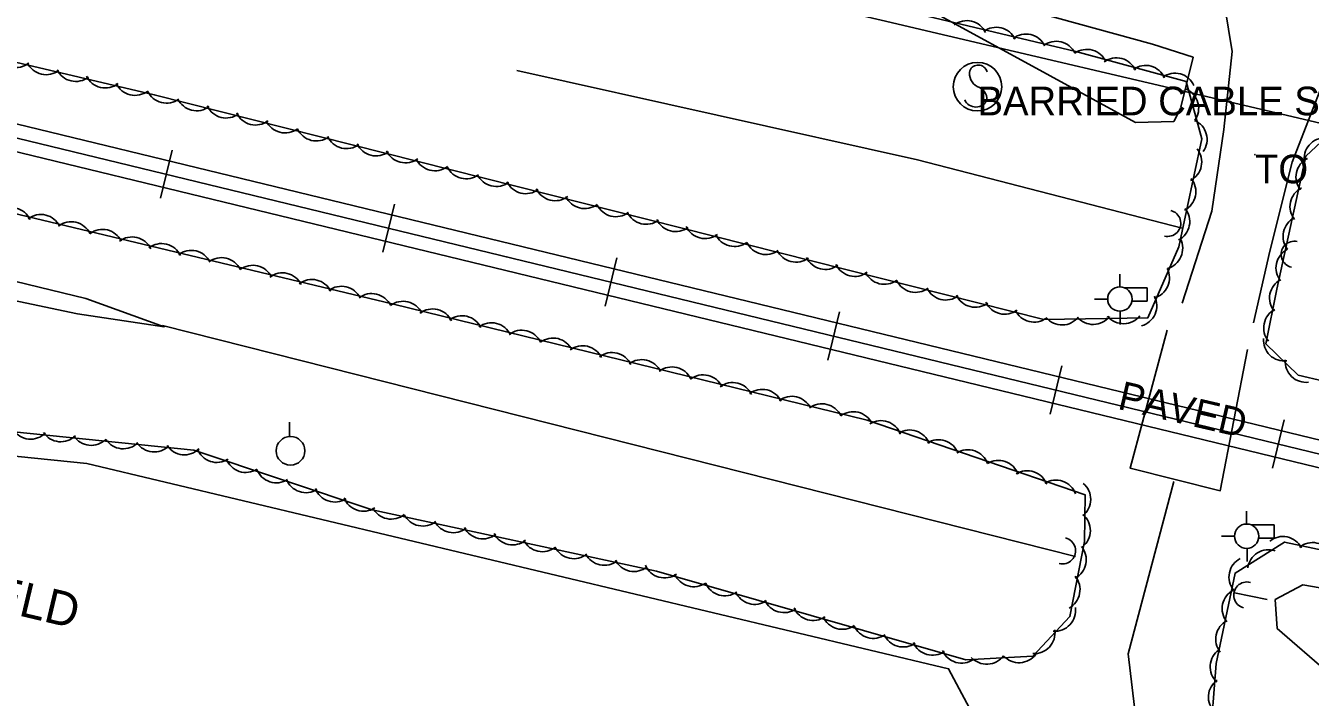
# Model space of a CAD drawing. Extents: x 1441650 to 1491889, y 345904 to 358319.
# Drawn here: x 1454014.1 to 1454238.7, y 352365.8 to 352483.1 of the extents above; entities that cross this region are included whole.
import ezdxf

# ---------------------------------------------------------------- set-up
doc = ezdxf.new("R2010")
doc.units = 0
for name, color, linetype in [('S_CROSS_DRAIN', 7, 'Continuous'), ('S_DITCHLINE', 7, 'Continuous'), ('S_GRAVEL_ROAD', 7, 'Continuous'), ('S_MISC_BOUNDARY', 7, 'Continuous'), ('S_MISC_BOUNDARY_ANNOT', 7, 'Continuous'), ('S_MSC_PT_SYM', 7, 'Continuous'), ('S_PARKING', 7, 'Continuous'), ('S_PARKING_ANNOT', 7, 'Continuous'), ('S_RAILROAD', 7, 'Continuous'), ('S_SIGN', 7, 'Continuous'), ('S_SIGN_ANNOT', 7, 'Continuous'), ('S_STREAM', 7, 'Continuous'), ('S_SURVEY_TEXT_ANNOT', 7, 'Continuous'), ('S_TRAILS', 7, 'Continuous'), ('S_TREE', 7, 'Continuous'), ('S_UTILITY_POLE', 7, 'Continuous')]:
    doc.layers.add(name, color=color, linetype=linetype)

msp = doc.modelspace()

# ---------------------------------------------------------------- linework, layer by layer
at = {"layer": 'S_CROSS_DRAIN'}
for centre, start, end in [((1454213.72, 352448.62), 255.9465, 76.2757), ((1454235.87, 352443.19), 77.6757, 258.0049), ((1454195.33, 352391.41), 256.306, 76.6352), ((1454227.58, 352383.66), 74.8593, 255.1885)]:
    msp.add_arc(centre, 2.3, start, end, dxfattribs=at)
at = {"layer": 'S_DITCHLINE'}
for points in [[(1454009.41, 352529.25), (1454021.93, 352526.19), (1454034.45, 352523.13), (1454046.97, 352520.07), (1454059.49, 352517.01), (1454072.01, 352513.95), (1454084.46, 352511.05), (1454096.91, 352508.15), (1454109.36, 352505.25), (1454121.81, 352502.35), (1454134.26, 352499.45), (1454146.71, 352496.55), (1454159.16, 352493.64), (1454171.6, 352490.74), (1454191.33, 352485.34), (1454211.05, 352479.93), (1454218.16, 352477.61), (1454216.01, 352468.91)], [(1454007.94, 352525.44), (1454020.6, 352522.38), (1454033.27, 352519.33), (1454045.93, 352516.28), (1454058.6, 352513.22), (1454071.26, 352510.17), (1454083.7, 352507.22), (1454096.14, 352504.28), (1454108.58, 352501.33), (1454121.02, 352498.39), (1454133.46, 352495.45), (1454145.9, 352492.5), (1454158.34, 352489.56), (1454170.78, 352486.61), (1454189.44, 352476.43), (1454208.09, 352466.25), (1454214.79, 352466.42), (1454216.02, 352468.81)]]:
    msp.add_lwpolyline(points, dxfattribs=at)
at = {"layer": 'S_GRAVEL_ROAD'}
for points in [[(1454217.36, 352502.05), (1454223.03, 352490.72), (1454224.98, 352478.61), (1454223.55, 352464.99), (1454221.42, 352450.76), (1454216.25, 352434.69)], [(1454228.71, 352431.22), (1454231.59, 352443.76), (1454235.46, 352459.28), (1454240.77, 352472.94), (1454247.94, 352481.75), (1454255.77, 352486.24), (1454264.22, 352491.06)]]:
    msp.add_lwpolyline(points, dxfattribs=at)
at = {"layer": 'S_MISC_BOUNDARY'}
msp.add_lwpolyline([(1454686.77, 352224.39), (1454629.36, 352232.66), (1454608.53, 352232.27), (1454586.68, 352227.2), (1454566.38, 352214.24), (1454512.68, 352151.16), (1454476.34, 352101.87), (1454455.06, 352090.76), (1454436.36, 352088.31), (1454415.71, 352093.38), (1454400.49, 352103.06), (1454359.73, 352141.03), (1454293.57, 352211.64), (1454232.27, 352285.07), (1454203.97, 352317.31), (1454175.42, 352370.8), (1454024.8, 352406.68), (1453982.48, 352410.96), (1453913.66, 352425.74), (1453821.25, 352446.56), (1453775.06, 352443.89), (1453762.03, 352438.86)], dxfattribs=at)
at = {"layer": 'S_MSC_PT_SYM'}
msp.add_lwpolyline([(1454228.99, 352460.61), (1454228.99, 352460.66), (1454228.99, 352460.61), (1454228.94, 352460.61), (1454228.99, 352460.61), (1454228.99, 352460.56), (1454228.99, 352460.61), (1454229.04, 352460.61)], dxfattribs=at)
at = {"layer": 'S_PARKING'}
msp.add_lwpolyline([(1454227.7, 352426.54), (1454222.93, 352401.89), (1454207.17, 352405.82), (1454213.61, 352429.97)], dxfattribs=at)
at = {"layer": 'S_RAILROAD'}
for p, q in [((1454039.71, 352461.41), (1454037.67, 352452.98)), ((1454039.25, 352459.5), (1454039.24, 352459.47)), ((1454038.14, 352454.93), (1454038.16, 352455.03)), ((1454078.59, 352451.98), (1454076.54, 352443.56)), ((1454078.13, 352450.08), (1454078.12, 352450.04)), ((1454077.02, 352445.5), (1454077.04, 352445.6)), ((1454117.46, 352442.56), (1454115.42, 352434.13)), ((1454117, 352440.65), (1454116.99, 352440.61)), ((1454205.37, 352437.49), (1454205.37, 352439.74)), ((1454115.89, 352436.07), (1454115.92, 352436.17)), ((1454203.28, 352435.36), (1454200.95, 352435.36)), ((1454210.17, 352437.34), (1454206.3, 352437.34)), ((1454210.17, 352435.01), (1454210.17, 352437.34)), ((1454156.34, 352433.13), (1454154.3, 352424.7)), ((1454205.45, 352430.94), (1454205.45, 352433.27)), ((1454210.17, 352435.01), (1454207.46, 352435.01)), ((1454155.88, 352431.22), (1454155.87, 352431.18)), ((1454154.77, 352426.64), (1454154.79, 352426.74)), ((1454195.22, 352423.7), (1454193.17, 352415.27)), ((1454194.75, 352421.79), (1454194.74, 352421.76)), ((1454193.64, 352417.22), (1454193.67, 352417.32)), ((1454234.09, 352414.27), (1454232.05, 352405.84)), ((1454233.63, 352412.36), (1454233.62, 352412.33)), ((1454232.52, 352407.79), (1454232.54, 352407.89)), ((1454227.53, 352396.06), (1454227.53, 352398.31)), ((1454232.33, 352395.91), (1454228.46, 352395.91)), ((1454232.33, 352393.58), (1454232.33, 352395.91)), ((1454225.44, 352393.93), (1454223.11, 352393.93)), ((1454232.33, 352393.58), (1454229.62, 352393.58)), ((1454227.61, 352389.51), (1454227.61, 352391.84))]:
    msp.add_line(p, q, dxfattribs=at)
for points in [[(1453358.93, 352624.5), (1454392.41, 352373.86)], [(1453358.37, 352622.19), (1454391.85, 352371.55)], [(1453357.82, 352619.92), (1454391.3, 352369.28)], [(1454038.66, 352457.21), (1454038.69, 352457.2)], [(1454077.54, 352447.78), (1454077.57, 352447.77)], [(1454116.41, 352438.35), (1454116.44, 352438.34)], [(1454155.29, 352428.92), (1454155.32, 352428.91)], [(1454194.17, 352419.49), (1454194.19, 352419.49)], [(1454233.04, 352410.07), (1454233.07, 352410.06)]]:
    msp.add_lwpolyline(points, dxfattribs=at)
for centre in [(1454205.37, 352435.38), (1454227.53, 352393.95)]:
    msp.add_circle(centre, 2.13, dxfattribs=at)
at = {"layer": 'S_SIGN'}
msp.add_circle((1454180.49, 352472.48), 4.24, dxfattribs=at)
for centre, radius, start, end in [((1454180.61, 352474.64), 1.62, 16.5258, 156.8957), ((1454181.65, 352474.74), 2.55, 167.1196, 241.9813), ((1454179.78, 352470.2), 2.38, 358.6529, 73.7063), ((1454180.22, 352471.09), 2.17, 204.641, 335.359)]:
    msp.add_arc(centre, radius, start, end, dxfattribs=at)
at = {"layer": 'S_STREAM'}
for points in [[(1453363.01, 352592.55), (1453479.22, 352563.13), (1453550.8, 352550.79), (1453596.82, 352540.94), (1453720.38, 352509.34), (1453785.64, 352491.93), (1453865.72, 352472.98), (1453954.81, 352452.44), (1454024.64, 352435.49), (1454038.35, 352430.55), (1454023.21, 352432.8), (1453961.95, 352445.68), (1453842.37, 352471.78), (1453782.84, 352484.13), (1453730.73, 352495.16), (1453675.19, 352509.46), (1453620.22, 352523.42), (1453558.76, 352539.42), (1453514.08, 352548.87), (1453463.46, 352558.22), (1453415.2, 352569.67), (1453358.6, 352584.91)], [(1454216.26, 352447.75), (1454169.98, 352459.71), (1454099.97, 352475.3)], [(1454038.01, 352430.77), (1454197.64, 352390.4)], [(1454231.13, 352382.87), (1454225.43, 352384.07)], [(1454388.13, 352330.44), (1454301.34, 352351.74), (1454251.8, 352365.75), (1454242.03, 352369.9), (1454232.87, 352377.8), (1454232.52, 352382.87), (1454237.35, 352385.48), (1454257.86, 352381.91), (1454259.92, 352381.42)]]:
    msp.add_lwpolyline(points, dxfattribs=at)
at = {"layer": 'S_TRAILS'}
msp.add_lwpolyline([(1454214.8, 352403.53), (1454206.82, 352373.39), (1454208.65, 352358.18), (1454219.53, 352337.35), (1454259.24, 352301.88), (1454319.02, 352237.9), (1454362.49, 352183.76), (1454390.07, 352144.22), (1454406.89, 352120.14), (1454417.78, 352112.14), (1454435.09, 352106.01), (1454444.99, 352103.91), (1454458.89, 352105.7), (1454468.76, 352112.18), (1454476.58, 352119.44), (1454489.64, 352134.63), (1454511.85, 352168.42), (1454538.41, 352200.75), (1454558.8, 352221.18), (1454581.02, 352236.48), (1454601.95, 352245.1), (1454625.41, 352246.67), (1454663.54, 352240.93), (1454687.4, 352237.14)], dxfattribs=at)
at = {"layer": 'S_TREE'}
for points in [[(1454092.49, 352503.66), (1454197.68, 352478.65), (1454216.97, 352473.38), (1454219.69, 352463.39), (1454215.69, 352444.49), (1454210.26, 352432.12), (1454192.07, 352431.82), (1454036.6, 352471.08), (1453849.04, 352515.24), (1453729.81, 352544.99), (1453559.38, 352584.91), (1453365.35, 352634.52)], [(1453368.83, 352604.5), (1453527.58, 352567.64), (1453619.06, 352545.33), (1453696.34, 352525.35), (1453759.99, 352511.03), (1453842.24, 352490.66), (1453918.96, 352472.74), (1454004.84, 352452.06), (1454078.18, 352434.55), (1454161.22, 352414.2), (1454199.28, 352401.19), (1454199.18, 352393.02), (1454196.64, 352379.91), (1454190.16, 352372.99), (1454178.43, 352372.37), (1454124.39, 352387.86), (1454074.7, 352398.58), (1454043.5, 352408.96), (1453992.52, 352414.17), (1453967.65, 352416.55)], [(1454008.21, 352520.91), (1454020.62, 352517.93), (1454033.03, 352514.95), (1454045.44, 352511.97), (1454057.86, 352508.99), (1454070.27, 352506.01), (1454093.61, 352500.54), (1454116.95, 352495.06), (1454140.3, 352489.58), (1454163.64, 352484.11), (1454186.98, 352478.63), (1454210.33, 352473.15), (1454233.67, 352467.68), (1454257.01, 352462.2)], [(1454008.21, 352520.91), (1454020.62, 352517.93), (1454033.03, 352514.95), (1454045.44, 352511.97), (1454057.86, 352508.99), (1454070.27, 352506.01), (1454093.61, 352500.54), (1454116.95, 352495.06), (1454140.3, 352489.58), (1454163.64, 352484.11), (1454186.98, 352478.63), (1454210.33, 352473.15), (1454233.67, 352467.68), (1454257.01, 352462.2)], [(1454448.79, 352371.34), (1454258.99, 352416.87), (1454236.55, 352422.09), (1454230.87, 352427.54), (1454232.8, 352437.08), (1454237.86, 352460.35), (1454245.03, 352467.03), (1454260.18, 352466.09), (1454313.24, 352456.44), (1454356.46, 352442.02)], [(1454288.48, 352317.63), (1454252.91, 352329.03), (1454235.01, 352340.76), (1454221.11, 352357.5), (1454222.18, 352371.72), (1454225.51, 352387.52), (1454234.15, 352392.92), (1454356.62, 352367.02), (1454510.53, 352327.65), (1454613.3, 352304.23), (1454719.52, 352277.82)]]:
    msp.add_lwpolyline(points, dxfattribs=at)
for centre, start, end in [((1454216.04, 352459.32), 297.2527, 38.8496), ((1454239.79, 352456.71), 116.9239, 218.5208), ((1454215.01, 352454.14), 297.2527, 38.8496), ((1454238.74, 352451.54), 116.9239, 218.5208), ((1454213.95, 352448.94), 297.2527, 38.8496), ((1454237.54, 352446.34), 116.9239, 218.5208), ((1454212.71, 352444.22), 285.4712, 27.0681), ((1454236.3, 352440.83), 116.9239, 218.5208), ((1454210.4, 352439.07), 285.4712, 27.0681), ((1454208.19, 352434.21), 285.4712, 27.0681), ((1454228.08, 352386.82), 117.3066, 218.9035), ((1454226.88, 352381.3), 117.3066, 218.9035), ((1454225.76, 352375.98), 117.3066, 218.9035), ((1454224.8, 352371.12), 124.8998, 226.4967), ((1454224.48, 352365.85), 124.8998, 226.4967)]:
    msp.add_arc(centre, 3.64, start, end, dxfattribs=at)
for centre, major_axis, ratio, start_param, end_param in [((1454178.62, 352480.37), (-3.57, 0.73), 0.999978, 3.793867, 5.567068), ((1454183.78, 352479.22), (-3.57, 0.73), 0.999978, 3.793867, 5.567068), ((1454188.95, 352478.03), (-3.57, 0.73), 0.999978, 3.793867, 5.567068), ((1454194.24, 352476.76), (-3.57, 0.73), 0.999978, 3.793867, 5.567068), ((1454199.62, 352475.36), (-3.51, 0.96), 0.999978, 3.825789, 5.598989), ((1454012.42, 352479.47), (3.55, -0.83), 0.999978, 3.825789, 5.598989), ((1454017.71, 352478.22), (3.55, -0.83), 0.999978, 3.825789, 5.598989), ((1454204.75, 352473.88), (-3.51, 0.96), 0.999978, 3.825789, 5.598989), ((1454209.86, 352472.56), (-3.51, 0.96), 0.999978, 3.825789, 5.598989), ((1454022.88, 352477.04), (3.55, -0.83), 0.999978, 3.825789, 5.598989), ((1454028.04, 352475.9), (3.55, -0.83), 0.999978, 3.825789, 5.598989), ((1454214.99, 352471.2), (-3.51, 0.96), 0.999978, 3.825789, 5.598989), ((1454033.22, 352474.61), (3.55, -0.83), 0.999978, 3.825789, 5.598989), ((1454038.74, 352473.25), (3.29, -1.57), 0.999977, 4.023994, 5.797194), ((1454215.51, 352468.72), (-0.96, 3.51), 0.999994, 3.825789, 5.598989), ((1454044.02, 352471.92), (3.29, -1.57), 0.999977, 4.023994, 5.797194), ((1454049.17, 352470.65), (3.29, -1.57), 0.999977, 4.023994, 5.797194), ((1454054.31, 352469.43), (3.29, -1.57), 0.999977, 4.023994, 5.797194), ((1454059.46, 352468.05), (3.29, -1.57), 0.999977, 4.023994, 5.797194), ((1454064.93, 352466.64), (3.29, -1.57), 0.999977, 4.023994, 5.797194), ((1454216.97, 352463.27), (-0.96, 3.51), 0.999994, 3.825788, 5.598989), ((1454070.2, 352465.3), (3.29, -1.57), 0.999977, 4.023994, 5.797194), ((1454075.35, 352464.04), (3.29, -1.57), 0.999977, 4.023994, 5.797194), ((1454241.23, 352459.9), (-2.67, -2.48), 0.999994, 3.825789, 5.598989), ((1454080.49, 352462.82), (3.29, -1.57), 0.999977, 4.023994, 5.797194), ((1454085.65, 352461.44), (3.29, -1.57), 0.999977, 4.023994, 5.797194), ((1454091.11, 352460.03), (3.29, -1.57), 0.999977, 4.023994, 5.797194), ((1454096.39, 352458.69), (3.29, -1.57), 0.999977, 4.023994, 5.797194), ((1454101.54, 352457.43), (3.29, -1.57), 0.999977, 4.023994, 5.797194), ((1454106.68, 352456.2), (3.29, -1.57), 0.999977, 4.023994, 5.797194), ((1454111.83, 352454.83), (3.29, -1.57), 0.999977, 4.023994, 5.797194), ((1454011.61, 352447.71), (-3.45, 1.18), 0.999612, 3.92082, 5.694021), ((1454117.3, 352453.41), (3.29, -1.57), 0.999977, 4.023994, 5.797194), ((1454016.78, 352446.51), (-3.45, 1.18), 0.999612, 3.92082, 5.694021), ((1454022.07, 352445.24), (-3.45, 1.18), 0.999612, 3.92082, 5.694021), ((1454122.58, 352452.08), (3.29, -1.57), 0.999977, 4.023994, 5.797194), ((1454127.73, 352450.81), (3.29, -1.57), 0.999977, 4.023994, 5.797194), ((1454027.55, 352443.9), (-3.45, 1.18), 0.999612, 3.92082, 5.694021), ((1454132.87, 352449.59), (3.29, -1.57), 0.999977, 4.023994, 5.797194), ((1454138.02, 352448.21), (3.29, -1.57), 0.999977, 4.023994, 5.797194), ((1454032.72, 352442.59), (-3.45, 1.18), 0.999612, 3.92082, 5.694021), ((1454037.88, 352441.43), (-3.45, 1.18), 0.999612, 3.92082, 5.694021), ((1454143.49, 352446.8), (3.29, -1.57), 0.999977, 4.023994, 5.797194), ((1454043.05, 352440.24), (-3.45, 1.18), 0.999612, 3.92082, 5.694021), ((1454048.34, 352438.97), (-3.45, 1.18), 0.999612, 3.92082, 5.694021), ((1454148.76, 352445.47), (3.29, -1.57), 0.999977, 4.023994, 5.797194), ((1454153.91, 352444.2), (3.29, -1.57), 0.999977, 4.023994, 5.797194), ((1454053.82, 352437.63), (-3.45, 1.18), 0.999612, 3.92082, 5.694021), ((1454059, 352436.32), (-3.45, 1.18), 0.999612, 3.92082, 5.694021), ((1454159.05, 352442.98), (3.29, -1.57), 0.999977, 4.023994, 5.797194), ((1454164.21, 352441.6), (3.29, -1.57), 0.999977, 4.023994, 5.797194), ((1454064.15, 352435.16), (-3.45, 1.18), 0.999612, 3.92082, 5.694021), ((1454069.32, 352433.97), (-3.45, 1.18), 0.999612, 3.92082, 5.694021), ((1454169.67, 352440.19), (3.29, -1.57), 0.999977, 4.023994, 5.797194), ((1454235.17, 352435.55), (3.55, -0.81), 0.999047, 2.280575, 4.053776), ((1454074.61, 352432.7), (-3.45, 1.18), 0.999612, 3.92082, 5.694021), ((1454174.95, 352438.85), (3.29, -1.57), 0.999977, 4.023994, 5.797194), ((1454180.1, 352437.59), (3.29, -1.57), 0.999977, 4.023994, 5.797194), ((1454080.07, 352431.35), (-3.54, 0.88), 0.999616, 3.829021, 5.602222), ((1454085.24, 352430.01), (-3.54, 0.88), 0.999616, 3.829021, 5.602222), ((1454185.24, 352436.37), (3.29, -1.57), 0.999977, 4.023994, 5.797194), ((1454190.39, 352434.99), (3.29, -1.57), 0.999977, 4.023994, 5.797194), ((1454234.15, 352430.35), (3.55, -0.81), 0.999047, 2.280575, 4.053776), ((1454090.39, 352428.82), (-3.54, 0.88), 0.999616, 3.829021, 5.602222), ((1454095.55, 352427.59), (-3.54, 0.88), 0.999616, 3.829021, 5.602222), ((1454195.27, 352434.5), (1.61, -3.27), 0.999889, 4.954782, 6.727983), ((1454200.71, 352434.59), (1.61, -3.27), 0.999889, 4.954782, 6.727983), ((1454206.01, 352434.71), (1.61, -3.27), 0.999889, 4.954782, 6.727983), ((1454100.83, 352426.29), (-3.54, 0.88), 0.999616, 3.829021, 5.602222), ((1454106.31, 352424.92), (-3.54, 0.88), 0.999616, 3.829021, 5.602222), ((1454111.47, 352423.58), (-3.54, 0.88), 0.999616, 3.829021, 5.602222), ((1454234.12, 352428.21), (3.05, 2), 0.999499, 2.479753, 4.252954), ((1454116.62, 352422.39), (-3.54, 0.88), 0.999616, 3.829021, 5.602222), ((1454121.78, 352421.16), (-3.54, 0.88), 0.999616, 3.829021, 5.602222), ((1454237.92, 352424.47), (3.05, 2), 0.999499, 2.479753, 4.252954), ((1454127.06, 352419.87), (-3.54, 0.88), 0.999616, 3.829021, 5.602222), ((1454132.54, 352418.49), (-3.54, 0.88), 0.999616, 3.829021, 5.602222), ((1454137.7, 352417.15), (-3.54, 0.88), 0.999616, 3.829021, 5.602222), ((1454142.85, 352415.96), (-3.54, 0.88), 0.999616, 3.829021, 5.602222), ((1454148.01, 352414.74), (-3.54, 0.88), 0.999616, 3.829021, 5.602222), ((1454153.3, 352413.44), (-3.54, 0.88), 0.999616, 3.829021, 5.602222), ((1454158.77, 352412.06), (-3.54, 0.88), 0.999616, 3.829021, 5.602222), ((1454163.62, 352410.5), (-3.45, 1.18), 0.999617, 3.825789, 5.598989), ((1454015, 352414.54), (3.62, -0.37), 0.999625, 3.825789, 5.598989), ((1454020.26, 352414.08), (3.62, -0.37), 0.999625, 3.825789, 5.598989), ((1454025.56, 352413.46), (3.62, -0.37), 0.999625, 3.825789, 5.598989), ((1454031.18, 352412.86), (3.62, -0.37), 0.999625, 3.825789, 5.598989), ((1454168.64, 352408.86), (-3.45, 1.18), 0.999617, 3.825789, 5.598989), ((1454173.67, 352407.17), (-3.45, 1.18), 0.999617, 3.825789, 5.598989), ((1454036.59, 352412.3), (3.62, -0.37), 0.999625, 3.825789, 5.598989), ((1454041.87, 352411.8), (3.62, -0.37), 0.999625, 3.825789, 5.598989), ((1454047.56, 352410.48), (3.46, -1.15), 0.999617, 3.825789, 5.598989), ((1454178.82, 352405.41), (-3.45, 1.18), 0.999617, 3.825789, 5.598989), ((1454052.6, 352408.73), (3.46, -1.15), 0.999617, 3.825789, 5.598989), ((1454184.15, 352403.55), (-3.45, 1.18), 0.999617, 3.825789, 5.598989), ((1454057.95, 352406.92), (3.46, -1.15), 0.999617, 3.825789, 5.598989), ((1454063.11, 352405.2), (3.46, -1.15), 0.999617, 3.825789, 5.598989), ((1454189.17, 352401.75), (-3.45, 1.18), 0.999617, 3.825789, 5.598989), ((1454194.19, 352400.11), (-3.45, 1.18), 0.999617, 3.825789, 5.598989), ((1454068.16, 352403.56), (3.46, -1.15), 0.999617, 3.825789, 5.598989), ((1454196.64, 352400.38), (0.04, 3.64), 0.999977, 3.825789, 5.598989), ((1454073.19, 352401.96), (3.46, -1.15), 0.999617, 3.825789, 5.598989), ((1454078.03, 352400.58), (2.92, -2.18), 0.999536, 4.254564, 6.027765), ((1454083.54, 352399.36), (2.92, -2.18), 0.999536, 4.254564, 6.027765), ((1454196.57, 352394.94), (0.04, 3.64), 0.999977, 3.825789, 5.598989), ((1454088.86, 352398.21), (2.92, -2.18), 0.999536, 4.254564, 6.027765), ((1454094.05, 352397.13), (2.92, -2.18), 0.999536, 4.254564, 6.027765), ((1454099.23, 352396.08), (2.92, -2.18), 0.999536, 4.254564, 6.027765), ((1454104.43, 352394.89), (2.92, -2.18), 0.999536, 4.254564, 6.027765), ((1454233.86, 352390.26), (-0.97, 3.51), 0.999911, 4.917556, 6.690757), ((1454239.06, 352389.2), (-0.97, 3.51), 0.999911, 4.917556, 6.690757), ((1454109.94, 352393.66), (2.92, -2.18), 0.999536, 4.254564, 6.027765), ((1454115.26, 352392.51), (2.92, -2.18), 0.999536, 4.254564, 6.027765), ((1454195.85, 352389.83), (0.69, 3.58), 0.999998, 3.825788, 5.598988), ((1454231.35, 352387.95), (-2.52, 2.63), 0.99974, 5.192121, 6.965321), ((1454120.45, 352391.43), (2.92, -2.18), 0.999536, 4.254564, 6.027765), ((1454125.8, 352390.3), (2.9, -2.2), 0.999558, 4.196239, 5.96944), ((1454130.9, 352388.76), (2.9, -2.2), 0.999558, 4.196239, 5.96944), ((1454194.76, 352384.61), (0.69, 3.58), 0.999998, 3.825788, 5.598988), ((1454136.32, 352387.17), (2.9, -2.2), 0.999558, 4.196239, 5.96944), ((1454141.55, 352385.67), (2.9, -2.2), 0.999558, 4.196239, 5.96944), ((1454146.66, 352384.24), (2.9, -2.2), 0.999558, 4.196239, 5.96944), ((1454151.76, 352382.86), (2.9, -2.2), 0.999558, 4.196239, 5.96944), ((1454193.99, 352380.98), (2.49, 2.66), 0.999915, 3.825789, 5.598989), ((1454156.87, 352381.32), (2.9, -2.2), 0.999558, 4.196239, 5.96944), ((1454162.28, 352379.73), (2.9, -2.2), 0.999558, 4.196239, 5.96944), ((1454190.4, 352377.08), (2.49, 2.66), 0.999915, 3.825789, 5.598989), ((1454167.51, 352378.23), (2.9, -2.2), 0.999558, 4.196239, 5.96944), ((1454172.62, 352376.8), (2.9, -2.2), 0.999558, 4.196239, 5.96944), ((1454177.72, 352375.41), (2.9, -2.2), 0.999558, 4.196239, 5.96944), ((1454182.1, 352375.23), (3.64, 0.19), 0.999652, 3.825789, 5.598989), ((1454187.74, 352375.49), (3.64, 0.19), 0.999652, 3.825789, 5.598989)]:
    msp.add_ellipse(centre, major_axis=major_axis, ratio=ratio, start_param=start_param, end_param=end_param, dxfattribs=at)
at = {"layer": 'S_UTILITY_POLE'}
msp.add_line((1454060.26, 352411.39), (1454060.26, 352413.87), dxfattribs=at)
msp.add_circle((1454060.41, 352408.87), 2.5, dxfattribs=at)

# ---------------------------------------------------------------- texts
at = {"layer": 'S_MISC_BOUNDARY_ANNOT'}
msp.add_text('CULTIVATED FIELD', height=6.0004, rotation=346.6626, dxfattribs=at).set_placement((1453949.81, 352395.05))
at = {"layer": 'S_PARKING_ANNOT'}
msp.add_text('PAVED', height=5, rotation=346.9634, dxfattribs=at).set_placement((1454204.81, 352416.22))
at = {"layer": 'S_SIGN_ANNOT'}
msp.add_text('BARRIED CABLE SPRINT', height=5, dxfattribs=at).set_placement((1454180.49, 352467.48))
at = {"layer": 'S_SURVEY_TEXT_ANNOT'}
msp.add_text('TO FIELD', height=5, dxfattribs=at).set_placement((1454228.99, 352455.61))

doc.saveas('drawing.dxf')
